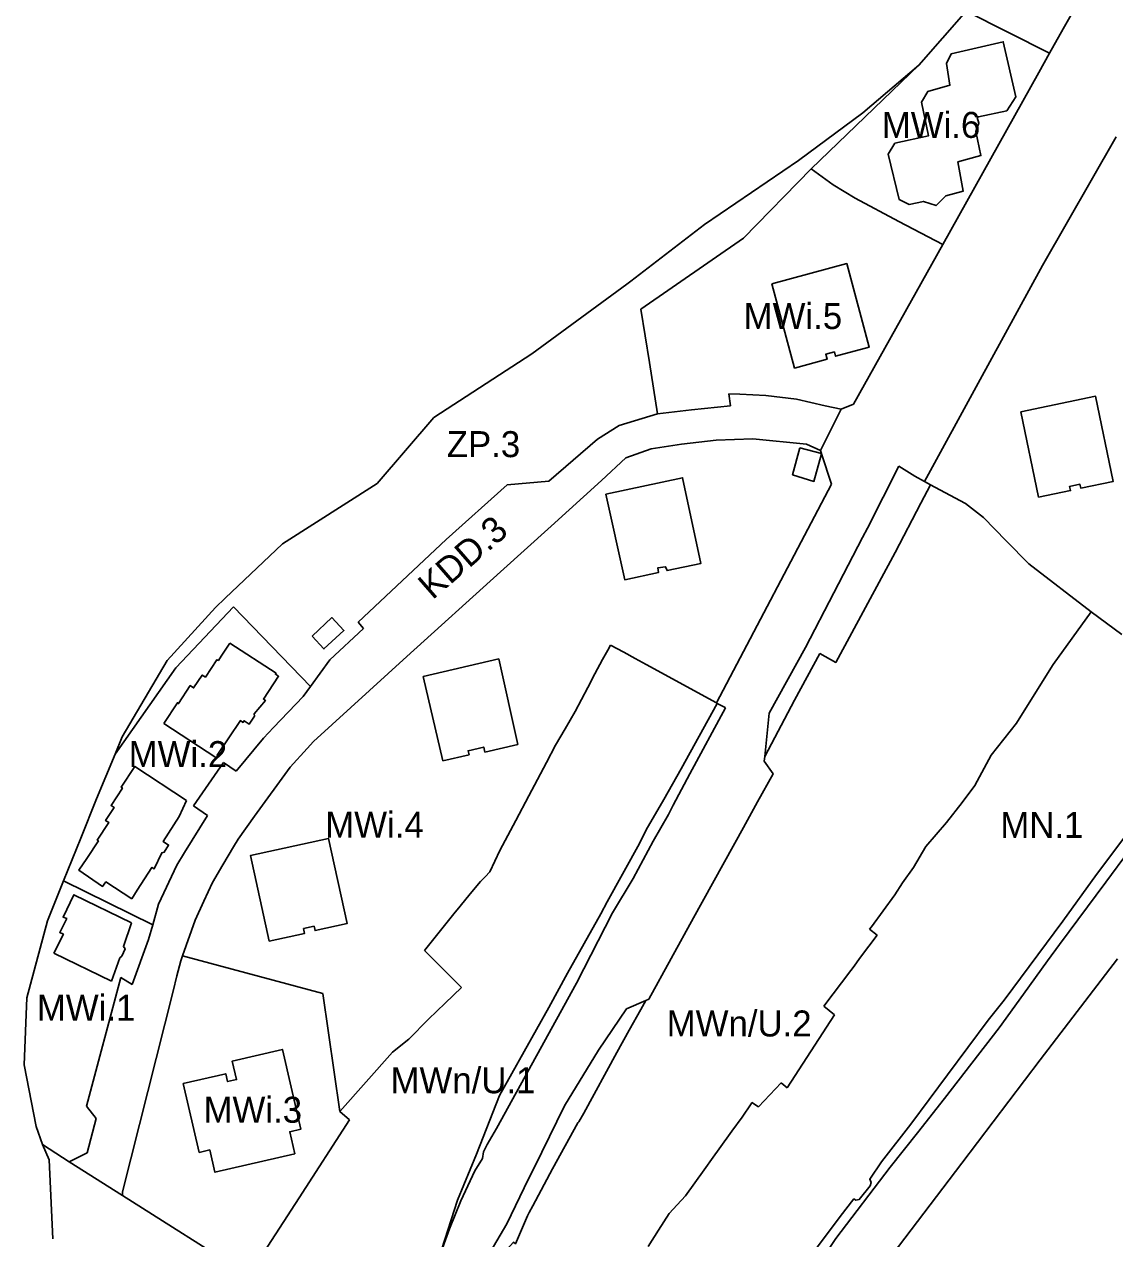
# Model space of a CAD drawing. Extents: x 7425067 to 7426806, y 5549054 to 5550619.
# Drawn here: x 7425292.1 to 7425501.8, y 5549946.2 to 5550179.8 of the extents above; entities that cross this region are included whole.
import ezdxf

# ---------------------------------------------------------------- set-up
doc = ezdxf.new("R2010")
doc.units = 0
for name, color, linetype in [('LIN_Linia Zabudowy Nieprzekraczalna', 7, 'Continuous'), ('LIN_linia zabudowy obowiązująca', 7, 'Continuous'), ('LIN_linie_rozgraniczajace', 7, 'Continuous'), ('TXT_Oznaczenia_przeznaczen', 7, 'Continuous')]:
    doc.layers.add(name, color=color, linetype=linetype)

msp = doc.modelspace()

# ---------------------------------------------------------------- linework, layer by layer
at = {"layer": 'LIN_Linia Zabudowy Nieprzekraczalna'}
for points in [[(7425466.4032, 5550091.2475), (7425464.5, 5550087.68), (7425459.55, 5550078.24), (7425448.17, 5550057.07), (7425445.1, 5550058.76)], [(7425491.83, 5550007.29), (7425498.3, 5550016.29), (7425502.79, 5550022.22), (7425507.22, 5550028.25), (7425515.07, 5550038.66), (7425522.31, 5550048.28), (7425524.87, 5550051.97), (7425530.95, 5550060.37), (7425534.51, 5550064.9), (7425537.18, 5550068.29), (7425543.69, 5550076.09)], [(7425445.1, 5550058.76), (7425440.25, 5550049.82), (7425434.4905, 5550038.9847)], [(7425367.1006, 5549942.0677), (7425369.63, 5549941.18), (7425371.78, 5549942.28), (7425375.41, 5549953.64), (7425379.09, 5549962.5), (7425383.52, 5549973.76), (7425392.98, 5549990.68), (7425396.6, 5549997.31), (7425402.98, 5550008.69), (7425404.23, 5550011.01), (7425410.43, 5550022.22), (7425411.71, 5550024.85), (7425415.09, 5550030.67), (7425418.41, 5550036.6), (7425425.3797, 5550049.1825)], [(7425434.4905, 5550038.9847), (7425434.4, 5550038.09), (7425436.0982, 5550035.6669), (7425433.12, 5550030.26)], [(7425433.12, 5550030.26), (7425430.41, 5550025.34), (7425420.82, 5550007.93), (7425412.21, 5549992.3), (7425411.6536, 5549992.0571)], [(7425480.51, 5549992.07), (7425491.83, 5550007.29)], [(7425411.6536, 5549992.0571), (7425410.6575, 5549990.2749), (7425408.4147, 5549986.3252), (7425406.0822, 5549982.0357), (7425399.7524, 5549970.374), (7425398.7566, 5549968.6855)], [(7425469.62, 5549977.72), (7425477.46, 5549988.24), (7425480.51, 5549992.07)], [(7425462.62, 5549968.26), (7425469.62, 5549977.72)], [(7425398.7566, 5549968.6855), (7425398.6261, 5549968.5893), (7425398.5769, 5549968.5036), (7425393.6834, 5549959.6655), (7425389.9392, 5549952.5103), (7425389.1819, 5549951.2183), (7425388.8947, 5549950.5772), (7425386.5508, 5549945.2404), (7425386.22, 5549945.54), (7425379.98, 5549938.66), (7425382.9229, 5549935.9972), (7425381.7632, 5549932.624)], [(7425431.7, 5549928.06), (7425436.81, 5549934.94), (7425444.07, 5549943.88), (7425449.03, 5549950.47), (7425451.65, 5549953.86), (7425452.01, 5549953.65), (7425452.67, 5549953.77), (7425454.76, 5549956.39), (7425454.96, 5549957.03), (7425454.71, 5549957.65), (7425456.96, 5549961.01), (7425462.62, 5549968.26)]]:
    msp.add_lwpolyline(points, dxfattribs=at)
at = {"layer": 'LIN_linia zabudowy obowiązująca'}
for points in [[(7425459.51, 5550156.94), (7425458.25, 5550154.82), (7425460.37, 5550146.11), (7425462.26, 5550145.15), (7425465, 5550145.75), (7425467.44, 5550144.95), (7425469.35, 5550146.82), (7425472.65, 5550147.71), (7425471.64, 5550153.37), (7425476.06, 5550154.58), (7425475.09, 5550159.22), (7425475.66, 5550160.83), (7425475.33, 5550161.91), (7425475.61, 5550162.06), (7425481.03, 5550163.18), (7425482.76, 5550165.86), (7425480.35, 5550176.49), (7425470.37, 5550174.16), (7425469.45, 5550172.26), (7425470.12, 5550168.1), (7425465.84, 5550166.89), (7425464.65, 5550164.85), (7425465.98, 5550158.37), (7425459.51, 5550156.94)], [(7425435.89, 5550129.92), (7425440.24, 5550113.7), (7425446.51, 5550115.39), (7425446.25, 5550116.37), (7425447.91, 5550116.82), (7425448.14, 5550115.97), (7425454.59, 5550117.7), (7425450.27, 5550133.79), (7425435.89, 5550129.92)], [(7425487.15, 5550088.84), (7425493.3, 5550090.12), (7425493.13, 5550090.93), (7425495.1, 5550091.34), (7425495.26, 5550090.6), (7425501.51, 5550091.9), (7425498.11, 5550108.27), (7425483.73, 5550105.28)], [(7425483.73, 5550105.28), (7425487.15, 5550088.84)], [(7425441.26, 5550098.35), (7425439.86, 5550093.17), (7425443.97, 5550091.9), (7425445.4471, 5550097.178), (7425445.47, 5550097.26), (7425445.4162, 5550097.2739), (7425441.26, 5550098.35)], [(7425403.9548, 5550089.4382), (7425407.58, 5550072.96), (7425414.08, 5550074.39), (7425413.92, 5550075.25), (7425415.45, 5550075.49), (7425415.73, 5550074.74), (7425422.23, 5550076.11), (7425418.71, 5550092.6), (7425403.9548, 5550089.4382)], [(7425347.47, 5550062.14), (7425349.76, 5550059.67), (7425353.58, 5550063.22), (7425351.3, 5550065.69), (7425347.47, 5550062.14)], [(7425318.94, 5550045.32), (7425328.96, 5550038.75), (7425329.28, 5550039.12), (7425329.19, 5550039.2), (7425333.68, 5550045.87), (7425334.18, 5550045.54), (7425334.39, 5550045.86), (7425335.39, 5550045.21), (7425336.39, 5550046.71), (7425336.32, 5550047.15), (7425338.51, 5550049.75), (7425338.12, 5550050.01), (7425341.02, 5550054.4), (7425340.43, 5550054.78), (7425340.54, 5550054.98), (7425331.65, 5550060.8)], [(7425331.65, 5550060.8), (7425329.9852, 5550058.2493), (7425329.47, 5550057.46), (7425329.18, 5550057.6), (7425326.95, 5550054.25), (7425326.34, 5550054.64), (7425324.69, 5550052.16), (7425324.06, 5550052.61), (7425321.81, 5550049.16), (7425321.57, 5550049.32), (7425318.94, 5550045.32)], [(7425368.83, 5550054.34), (7425372.63, 5550038.14), (7425377.66, 5550039.32), (7425377.48, 5550040.08), (7425380.47, 5550040.78), (7425380.7, 5550039.83), (7425387.01, 5550041.3), (7425383.35, 5550057.75), (7425368.83, 5550054.34)], [(7425323.33, 5550030.49), (7425313.42, 5550037.05), (7425310.78, 5550033.06), (7425311.01, 5550032.89), (7425308.81, 5550029.54), (7425309.43, 5550029.15), (7425307.77, 5550026.66), (7425308.42, 5550026.26), (7425306.16, 5550022.88), (7425306.4, 5550022.73), (7425304.17, 5550019.35), (7425302.65, 5550017.09), (7425307.2, 5550013.98), (7425307.84, 5550014.86), (7425312.7877, 5550011.6063)], [(7425312.7877, 5550011.6063), (7425313.85, 5550013.26), (7425316.67, 5550017.65), (7425317.12, 5550017.37), (7425318.58, 5550020.41), (7425319.04, 5550020.6), (7425319.89, 5550021.94), (7425318.87, 5550022.6), (7425321.94, 5550027.44), (7425323.33, 5550030.49)], [(7425339.24, 5550003.45), (7425346.03, 5550004.94), (7425345.83, 5550005.87), (7425347.86, 5550006.32), (7425348.05, 5550005.48), (7425354.21, 5550006.83), (7425350.61, 5550023.2), (7425335.63, 5550019.9), (7425339.24, 5550003.45)], [(7425312.72, 5550006.95), (7425301.69, 5550012.38), (7425299.61, 5550008.09), (7425300.29, 5550007.78), (7425298.96, 5550005.1), (7425299.65, 5550004.77), (7425297.82, 5550001.11)], [(7425308.93, 5549995.72), (7425310.49, 5550000.24), (7425310.91, 5550000.57), (7425311.52, 5550001.96), (7425311.2, 5550002.45), (7425312.72, 5550006.95)], [(7425297.82, 5550001.11), (7425308.93, 5549995.72)], [(7425325.7604, 5549962.8201), (7425327.79, 5549963.29), (7425328.78, 5549959), (7425344.15, 5549962.55), (7425343.18, 5549966.77), (7425345.3, 5549967.26), (7425341.76, 5549982.61), (7425332.12, 5549980.39), (7425332.94, 5549976.82), (7425331.22, 5549976.43), (7425330.87, 5549977.94), (7425322.71, 5549976.06), (7425325.7604, 5549962.8201)]]:
    msp.add_lwpolyline(points, dxfattribs=at)
at = {"layer": 'LIN_linie_rozgraniczajace'}
for points in [[(7425514.36, 5550218.44), (7425491.87, 5550178.96)], [(7425464.15, 5550171.97), (7425473.21, 5550182.39)], [(7425489.2647, 5550174.2827), (7425473.21, 5550182.39)], [(7425491.87, 5550178.96), (7425489.2647, 5550174.2827)], [(7425489.2647, 5550174.2827), (7425487.18, 5550170.54)], [(7425443.43, 5550152), (7425464.15, 5550171.97)], [(7425453.38, 5550162.78), (7425464.15, 5550171.97)], [(7425487.18, 5550170.54), (7425468.72, 5550137.44)], [(7425440.98, 5550153.66), (7425453.38, 5550162.78)], [(7425487.94, 5550133.45), (7425502.07, 5550158.18)], [(7425422.93, 5550141.34), (7425440.98, 5550153.66)], [(7425443.43, 5550152), (7425430.45, 5550138.67)], [(7425443.43, 5550152), (7425447.68, 5550148.96)], [(7425447.68, 5550148.96), (7425451.9, 5550146.39)], [(7425451.9, 5550146.39), (7425460.31, 5550141.915)], [(7425408.74, 5550130.43), (7425422.93, 5550141.34)], [(7425460.31, 5550141.915), (7425468.72, 5550137.44)], [(7425430.45, 5550138.67), (7425410.68, 5550125.05)], [(7425468.72, 5550137.44), (7425451.59, 5550106.73)], [(7425475.53, 5550110.77), (7425487.94, 5550133.45)], [(7425389.71, 5550116.43), (7425407.96, 5550129.83)], [(7425407.96, 5550129.83), (7425408.74, 5550130.43)], [(7425410.68, 5550125.05), (7425412.33, 5550114.77)], [(7425370.86, 5550104.18), (7425389.71, 5550116.43)], [(7425412.33, 5550114.77), (7425413.9148, 5550104.8965)], [(7425465.19, 5550091.9), (7425475.53, 5550110.77)], [(7425429.69, 5550108.65), (7425427.63, 5550108.77)], [(7425427.63, 5550108.77), (7425427.93, 5550106.43)], [(7425434.7, 5550108.45), (7425429.69, 5550108.65)], [(7425440.58, 5550107.69), (7425434.7, 5550108.45)], [(7425446.09, 5550106.46), (7425440.58, 5550107.69)], [(7425420.45, 5550105.67), (7425413.9148, 5550104.8965)], [(7425427.93, 5550106.43), (7425420.45, 5550105.67)], [(7425449.22, 5550105.79), (7425445.24, 5550097.82)], [(7425449.22, 5550105.79), (7425446.09, 5550106.46)], [(7425451.59, 5550106.73), (7425449.22, 5550105.79)], [(7425360, 5550091.47), (7425370.86, 5550104.18)], [(7425406.53, 5550102.67), (7425402.33, 5550100.03)], [(7425413.86, 5550104.89), (7425406.53, 5550102.67)], [(7425413.9148, 5550104.8965), (7425413.86, 5550104.89)], [(7425402.33, 5550100.03), (7425392.97, 5550091.91)], [(7425412.65, 5550098.15), (7425407.81, 5550096.45)], [(7425418.52, 5550099.04), (7425412.65, 5550098.15)], [(7425425.19, 5550099.81), (7425418.52, 5550099.04)], [(7425432.21, 5550100.08), (7425425.19, 5550099.81)], [(7425442.54, 5550099.06), (7425432.21, 5550100.08)], [(7425445.24, 5550097.82), (7425442.54, 5550099.06)], [(7425407.81, 5550096.45), (7425403.14, 5550092.1)], [(7425445.24, 5550097.82), (7425445.4162, 5550097.2739), (7425445.4471, 5550097.178), (7425447.33, 5550091.34)], [(7425454.23, 5550082.88), (7425460.29, 5550094.85)], [(7425460.29, 5550094.85), (7425463.37, 5550092.88)], [(7425341.78, 5550079.86), (7425360, 5550091.47)], [(7425385, 5550091.25), (7425373.26, 5550080.72)], [(7425392.97, 5550091.91), (7425385, 5550091.25)], [(7425403.14, 5550092.1), (7425393.43, 5550083.295)], [(7425447.33, 5550091.34), (7425425.22, 5550049.27)], [(7425463.37, 5550092.88), (7425465.19, 5550091.9)], [(7425469.15, 5550089.77), (7425466.4032, 5550091.2475), (7425465.19, 5550091.9)], [(7425473.11, 5550087.64), (7425469.15, 5550089.77)], [(7425474.845, 5550086.295), (7425473.11, 5550087.64)], [(7425476.58, 5550084.95), (7425474.845, 5550086.295)], [(7425480.935, 5550080.485), (7425476.58, 5550084.95)], [(7425393.43, 5550083.295), (7425383.72, 5550074.49)], [(7425453.32, 5550081.11), (7425454.23, 5550082.88)], [(7425330.79, 5550069.41), (7425341.78, 5550079.86)], [(7425373.26, 5550080.72), (7425356.3191, 5550064.8268)], [(7425447.81, 5550070.45), (7425453.32, 5550081.11)], [(7425485.29, 5550076.02), (7425480.935, 5550080.485)], [(7425497.26, 5550066.78), (7425485.29, 5550076.02)], [(7425383.72, 5550074.49), (7425365.72, 5550058.18)], [(7425442.37, 5550059.93), (7425447.81, 5550070.45)], [(7425319.6, 5550057.42), (7425328.9, 5550067.62)], [(7425332.3727, 5550067.7725), (7425321.2504, 5550056.0387)], [(7425328.9, 5550067.62), (7425330.79, 5550069.41)], [(7425347.1734, 5550052.465), (7425332.3727, 5550067.7725)], [(7425497.26, 5550066.78), (7425489.96, 5550056.68)], [(7425503.16, 5550062.43), (7425497.26, 5550066.78)], [(7425357.33, 5550063.62), (7425350.91, 5550057.59)], [(7425356.3191, 5550064.8268), (7425357.33, 5550063.62)], [(7425403.335, 5550057.62), (7425404.3144, 5550059.415)], [(7425404.3144, 5550059.415), (7425404.83, 5550060.36)], [(7425404.83, 5550060.36), (7425407.39, 5550059.04)], [(7425407.39, 5550059.04), (7425409.56, 5550057.85)], [(7425435.33, 5550047.28), (7425442.37, 5550059.93)], [(7425321.2504, 5550056.0387), (7425309.5865, 5550039.4318)], [(7425310.98, 5550042.77), (7425319.6, 5550057.42)], [(7425350.91, 5550057.59), (7425347.1734, 5550052.465)], [(7425365.72, 5550058.18), (7425347.72, 5550041.87)], [(7425401.84, 5550054.88), (7425403.335, 5550057.62)], [(7425409.56, 5550057.85), (7425411.73, 5550056.66)], [(7425411.73, 5550056.66), (7425425.22, 5550049.27)], [(7425489.96, 5550056.68), (7425484.36, 5550047.75)], [(7425400.46, 5550052.215), (7425401.84, 5550054.88)], [(7425347.1734, 5550052.465), (7425345.7452, 5550050.5062)], [(7425398.075, 5550047.62), (7425400.46, 5550052.215)], [(7425345.7452, 5550050.5062), (7425340.0838, 5550044.5804)], [(7425425.22, 5550049.27), (7425425.3797, 5550049.1825), (7425426.87, 5550048.38)], [(7425396.12, 5550044.285), (7425398.075, 5550047.62)], [(7425426.98, 5550048.31), (7425420.09, 5550035.61)], [(7425426.87, 5550048.38), (7425426.98, 5550048.31)], [(7425434.4, 5550038.09), (7425434.4905, 5550038.9847), (7425435.33, 5550047.28)], [(7425484.36, 5550047.75), (7425482.89, 5550045.41)], [(7425340.0838, 5550044.5804), (7425338.14, 5550042.47)], [(7425394.27, 5550041.15), (7425396.12, 5550044.285)], [(7425482.89, 5550045.41), (7425478.05, 5550039.25)], [(7425309.5865, 5550039.4318), (7425310.98, 5550042.77)], [(7425338.14, 5550042.47), (7425332.8471, 5550036.1248)], [(7425347.72, 5550041.87), (7425346.53, 5550040.54)], [(7425346.53, 5550040.54), (7425343.26, 5550036.9)], [(7425392.54, 5550037.835), (7425394.27, 5550041.15)], [(7425306, 5550030.84), (7425309.5865, 5550039.4318)], [(7425330.4291, 5550037.8086), (7425324.6488, 5550029.4582)], [(7425332.8471, 5550036.1248), (7425330.4291, 5550037.8086)], [(7425390.81, 5550034.52), (7425392.54, 5550037.835)], [(7425436.0982, 5550035.6669), (7425434.4, 5550038.09)], [(7425478.05, 5550039.25), (7425474.92, 5550033.38)], [(7425343.26, 5550036.9), (7425336.41, 5550027.49)], [(7425420.09, 5550035.61), (7425416.89, 5550029.64)], [(7425433.12, 5550030.26), (7425436.0982, 5550035.6669)], [(7425389.16, 5550031.425), (7425390.81, 5550034.52)], [(7425474.92, 5550033.38), (7425472.49, 5550030.13)], [(7425303, 5550023.25), (7425306, 5550030.84)], [(7425386.62, 5550026.64), (7425389.16, 5550031.425)], [(7425430.41, 5550025.34), (7425433.12, 5550030.26)], [(7425324.6488, 5550029.4582), (7425327.3458, 5550027.6024)], [(7425416.03, 5550027.84), (7425413.06, 5550022.7)], [(7425416.89, 5550029.64), (7425416.03, 5550027.84)], [(7425472.49, 5550030.13), (7425469.44, 5550026.25)], [(7425327.3458, 5550027.6024), (7425322.97, 5550020.49)], [(7425336.41, 5550027.49), (7425333.29, 5550023.05)], [(7425383.57, 5550020.89), (7425386.62, 5550026.64)], [(7425469.44, 5550026.25), (7425465.45, 5550021.69)], [(7425299.7, 5550015.03), (7425303, 5550023.25)], [(7425420.82, 5550007.93), (7425430.41, 5550025.34)], [(7425332.34, 5550021.58), (7425330.325, 5550018.16)], [(7425333.29, 5550023.05), (7425332.34, 5550021.58)], [(7425382.595, 5550018.835), (7425383.57, 5550020.89)], [(7425413.06, 5550022.7), (7425409.19, 5550015.53)], [(7425465.45, 5550021.69), (7425463.1, 5550017.62)], [(7425500.08, 5550014.81), (7425504.63, 5550020.95)], [(7425322.97, 5550020.49), (7425321.49, 5550018.04)], [(7425381.62, 5550016.78), (7425382.595, 5550018.835)], [(7425321.49, 5550018.04), (7425317.95, 5550010.54)], [(7425330.325, 5550018.16), (7425328.31, 5550014.74)], [(7425380.725, 5550015.845), (7425381.62, 5550016.78)], [(7425463.1, 5550017.62), (7425461.02, 5550014.65)], [(7425296.62, 5550007.38), (7425299.7, 5550015.03)], [(7425299.7, 5550015.03), (7425316.8361, 5550006.5916)], [(7425328.31, 5550014.74), (7425326.635, 5550011.12)], [(7425377.885, 5550012.55), (7425379.83, 5550014.91)], [(7425379.83, 5550014.91), (7425380.725, 5550015.845)], [(7425409.19, 5550015.53), (7425405.21, 5550008.92)], [(7425461.02, 5550014.65), (7425459.51, 5550012.39)], [(7425491.18, 5550002.83), (7425500.08, 5550014.81)], [(7425375.94, 5550010.19), (7425377.885, 5550012.55)], [(7425459.51, 5550012.39), (7425455, 5550006.2)], [(7425317.95, 5550010.54), (7425316.8361, 5550006.5916)], [(7425326.635, 5550011.12), (7425324.96, 5550007.5)], [(7425374.74, 5550008.69), (7425375.94, 5550010.19)], [(7425292.61, 5549992.55), (7425296.62, 5550007.38)], [(7425324.96, 5550007.5), (7425322.55, 5550000.63)], [(7425369.08, 5550001.63), (7425374.74, 5550008.69)], [(7425405.21, 5550008.92), (7425398.29, 5549995.36)], [(7425412.21, 5549992.3), (7425420.82, 5550007.93)], [(7425316.8361, 5550006.5916), (7425316.04, 5550003.77)], [(7425456.09, 5550004.62), (7425452.89, 5550000.39)], [(7425455, 5550006.2), (7425454.65, 5550005.73)], [(7425454.65, 5550005.73), (7425456.09, 5550004.62)], [(7425316.04, 5550003.77), (7425312.91, 5549995.11)], [(7425488.9, 5549999.67), (7425491.18, 5550002.83)], [(7425322.55, 5550000.63), (7425322.22, 5549999.69)], [(7425322.55, 5550000.63), (7425349.52, 5549993.38)], [(7425376.22, 5549994.55), (7425369.08, 5550001.63)], [(7425452.89, 5550000.39), (7425451.51, 5549998.41)], [(7425502.33, 5550000.03), (7425487.47, 5549980.59)], [(7425322.22, 5549999.69), (7425321.49, 5549996.755)], [(7425451.08, 5549997.82), (7425445.88, 5549990.95)], [(7425451.51, 5549998.41), (7425451.08, 5549997.82)], [(7425484.26, 5549993.22), (7425488.9, 5549999.67)], [(7425310.7144, 5549996.4362), (7425304.1, 5549971.73)], [(7425312.91, 5549995.11), (7425310.7144, 5549996.4362)], [(7425321.49, 5549996.755), (7425320.76, 5549993.82)], [(7425398.29, 5549995.36), (7425382.91, 5549967.42)], [(7425320.76, 5549993.82), (7425315.905, 5549974.52)], [(7425349.52, 5549993.38), (7425352.79, 5549970.69)], [(7425373.05, 5549991.49), (7425376.22, 5549994.55)], [(7425479.6, 5549986.77), (7425484.26, 5549993.22)], [(7425292.14, 5549979.67), (7425292.61, 5549992.55)], [(7425369.88, 5549988.43), (7425373.05, 5549991.49)], [(7425407.95, 5549990.44), (7425411.6536, 5549992.0571), (7425412.21, 5549992.3)], [(7425445.88, 5549990.95), (7425447.9, 5549989.27)], [(7425366.08, 5549984.6), (7425369.88, 5549988.43)], [(7425402.53, 5549982.45), (7425407.95, 5549990.44)], [(7425447.9, 5549989.27), (7425438.84, 5549975.24)], [(7425469.07, 5549973.16), (7425479.6, 5549986.77)], [(7425362.94, 5549982.11), (7425366.08, 5549984.6)], [(7425352.79, 5549970.69), (7425362.94, 5549982.11)], [(7425395.99, 5549971.74), (7425402.53, 5549982.45)], [(7425294.44, 5549967.79), (7425292.14, 5549979.67)], [(7425487.47, 5549980.59), (7425472.43, 5549960.77)], [(7425315.905, 5549974.52), (7425311.05, 5549955.22)], [(7425437.66, 5549976.18), (7425433.29, 5549971.59)], [(7425438.84, 5549975.24), (7425437.66, 5549976.18)], [(7425431.87, 5549972.16), (7425430.18, 5549969.59)], [(7425432.04, 5549972.41), (7425431.87, 5549972.16)], [(7425433.29, 5549971.59), (7425432.04, 5549972.41)], [(7425463.85, 5549966.58), (7425469.07, 5549973.16)], [(7425304.1, 5549971.73), (7425305.985, 5549969.32)], [(7425354.68, 5549969.05), (7425352.79, 5549970.69)], [(7425391.64, 5549962.88), (7425395.99, 5549971.74)], [(7425430.18, 5549969.59), (7425428.17, 5549966.9)], [(7425295.65, 5549964.3), (7425294.44, 5549967.79)], [(7425305.985, 5549969.32), (7425304.2259, 5549962.7189)], [(7425344.995, 5549954.085), (7425354.68, 5549969.05)], [(7425382.91, 5549967.42), (7425381.13, 5549964.34)], [(7425428.17, 5549966.9), (7425425.75, 5549963.52)], [(7425458.63, 5549960), (7425463.85, 5549966.58)], [(7425296.91, 5549961.35), (7425295.65, 5549964.3)], [(7425300.7929, 5549961.0187), (7425295.65, 5549964.3)], [(7425304.2259, 5549962.7189), (7425300.7929, 5549961.0187)], [(7425380.46, 5549962.91), (7425380.22, 5549961.64)], [(7425381.13, 5549964.34), (7425380.46, 5549962.91)], [(7425388.275, 5549955.975), (7425391.64, 5549962.88)], [(7425425.75, 5549963.52), (7425424.58, 5549961.89)], [(7425297.65, 5549946.19), (7425296.91, 5549961.35)], [(7425311.01, 5549954.5), (7425300.7929, 5549961.0187)], [(7425380.22, 5549961.64), (7425378.75, 5549959.25)], [(7425424.58, 5549961.89), (7425422.88, 5549959.46)], [(7425472.43, 5549960.77), (7425459.01, 5549943.13)], [(7425378.75, 5549959.25), (7425376.04, 5549953.48)], [(7425422.88, 5549959.46), (7425421.065, 5549956.945)], [(7425448.18, 5549946.22), (7425458.63, 5549960)], [(7425384.91, 5549949.07), (7425388.275, 5549955.975)], [(7425421.065, 5549956.945), (7425419.25, 5549954.43)], [(7425311.05, 5549955.22), (7425311.01, 5549954.5)], [(7425335.31, 5549939.12), (7425311.01, 5549954.5)], [(7425335.31, 5549939.12), (7425335.8824, 5549940.0045), (7425344.995, 5549954.085)], [(7425376.04, 5549953.48), (7425373.88, 5549948.075)], [(7425419.25, 5549954.43), (7425417.68, 5549952.73)], [(7425416.11, 5549951.03), (7425414.065, 5549947.82)], [(7425417.68, 5549952.73), (7425416.11, 5549951.03)], [(7425379.36, 5549939.6), (7425384.91, 5549949.07)], [(7425373.88, 5549948.075), (7425371.78, 5549942.28), (7425370.99, 5549940.85)], [(7425414.065, 5549947.82), (7425412.11, 5549944.71)], [(7425445.78, 5549942.63), (7425448.18, 5549946.22)]]:
    msp.add_lwpolyline(points, dxfattribs=at)

# ---------------------------------------------------------------- texts
at = {"layer": 'TXT_Oznaczenia_przeznaczen'}
for s, p in [('MWi.6', (7425457.0063, 5550157.9799)), ('MWi.5', (7425430.4443, 5550121.2075)), ('ZP.3', (7425373.3644, 5550096.5601)), ('MWi.2', (7425312.2105, 5550036.9296)), ('MWi.4', (7425350.0034, 5550023.343)), ('MN.1', (7425479.7984, 5550023.3158)), ('MWi.1', (7425294.5581, 5549988.1303)), ('MWn/U.2', (7425415.6538, 5549985.1097)), ('MWn/U.1', (7425362.5557, 5549974.1837)), ('MWi.3', (7425326.608, 5549968.5141))]:
    msp.add_text(s, height=5, dxfattribs=at).set_placement(p)
msp.add_text('KDD.3', height=5, rotation=41.015755, dxfattribs=at).set_placement((7425370.6242, 5550068.9884))

doc.saveas('drawing.dxf')
